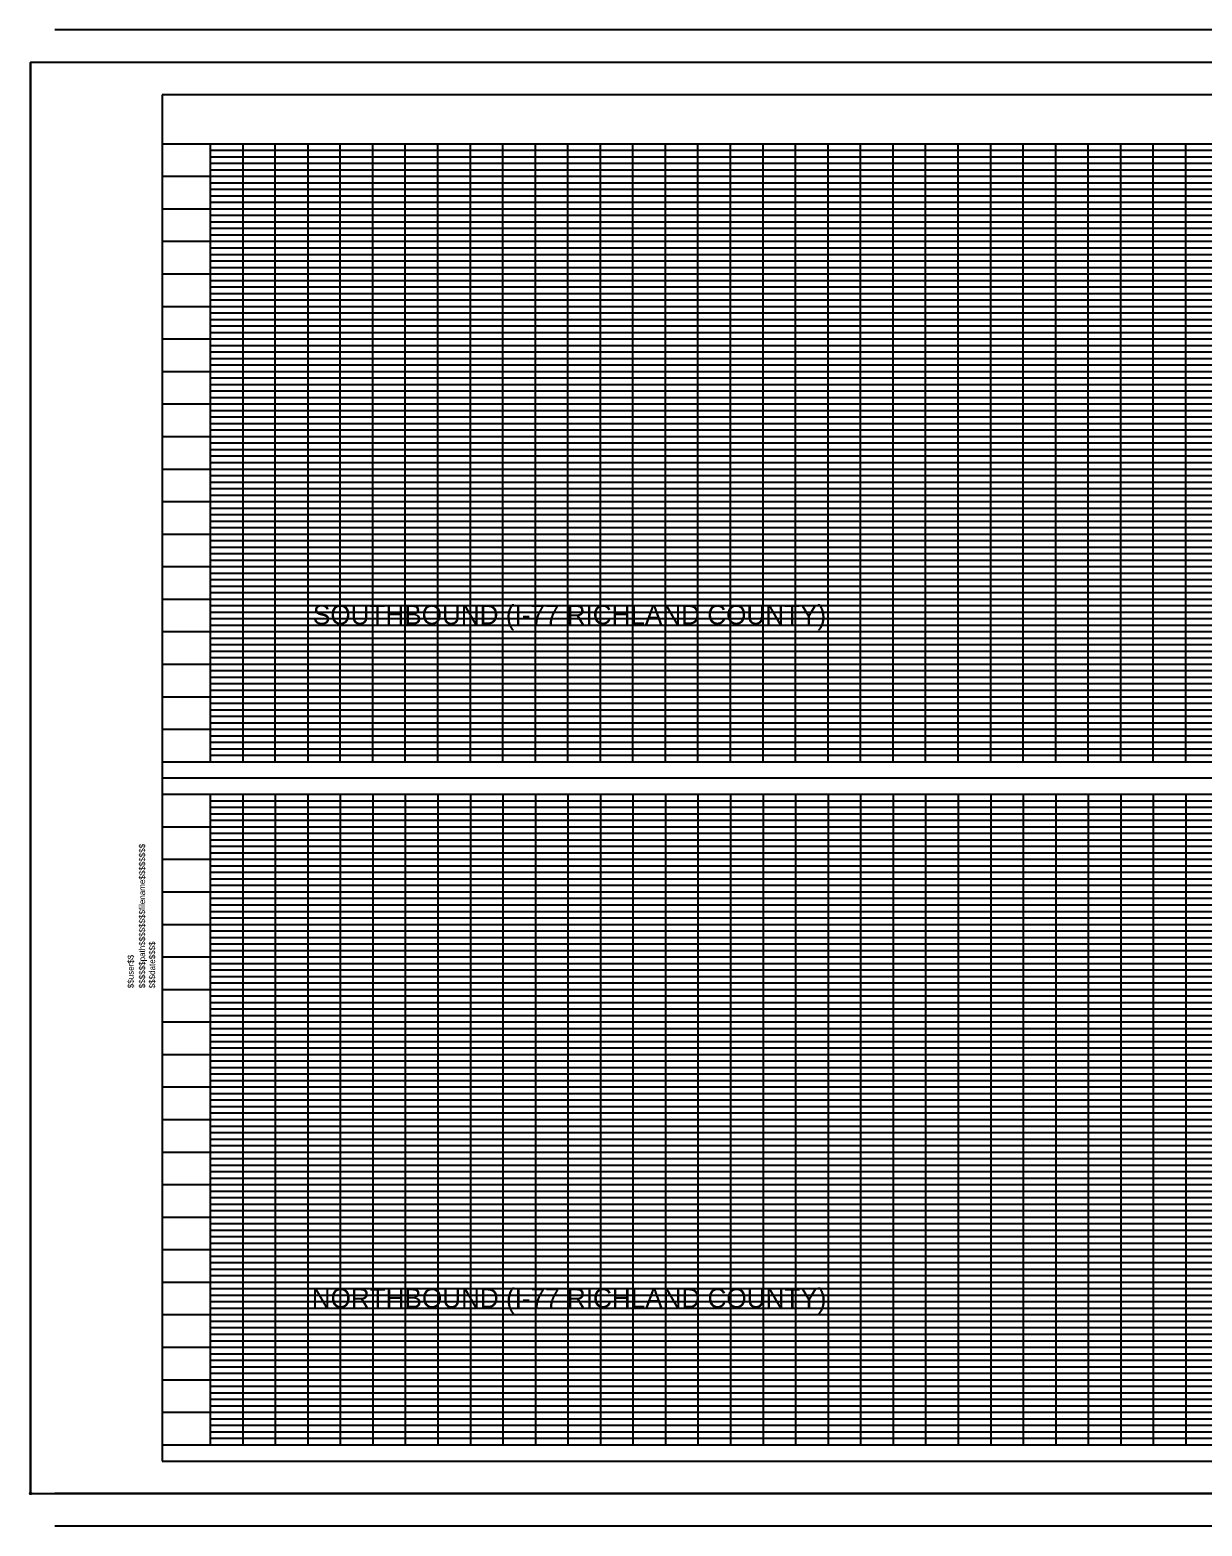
# Model space of a CAD drawing. Extents: x -187 to 1610, y -563 to 587.
# Drawn here: x -187 to 714, y -563 to 587 of the extents above; entities that cross this region are included whole.
import ezdxf

# ---------------------------------------------------------------- set-up
doc = ezdxf.new("R2010")
doc.units = 0
for name, color, linetype in [('Default', 7, 'Continuous'), ('RD_SHT_Bndy', 7, 'Continuous'), ('RD_SHT_ID', 7, 'Continuous'), ('RD_SHT_IplotShp', 7, 'Continuous'), ('RD_SHT_MjGrid', 7, 'Continuous'), ('RD_SHT_MnGrid', 7, 'Continuous'), ('RD_SHT_Snap', 7, 'Continuous'), ('RD_SHT_SubGrid', 7, 'Continuous')]:
    doc.layers.add(name, color=color, linetype=linetype)

msp = doc.modelspace()

# ---------------------------------------------------------------- linework, layer by layer
at = {"layer": 'RD_SHT_Bndy'}
for p, q in [((1592.6, 587.5), (-167.4, 587.5)), ((1592.6, 562.5), (-167.4, 562.5)), ((-85, 537.5), (-85, -512.5)), ((1590, 537.5), (-85, 537.5)), ((-85.5, 500), (1590, 500)), ((-48, 500), (-48, 25)), ((-85, 25), (1590, 25)), ((-85, 12.5), (1590, 12.5)), ((-85, 0), (1590, 0)), ((-48, 0), (-48, -500)), ((-85, -500), (1590.3, -500)), ((-85, -512.5), (1590, -512.5)), ((1592.6, -537.5), (-167.4, -537.5)), ((1592.6, -562.5), (-167.4, -562.5))]:
    msp.add_line(p, q, dxfattribs=at)
at = {"layer": 'RD_SHT_IplotShp'}
msp.add_lwpolyline([(1610, 562.5), (-186, 562.5), (-186, -537.5), (1610, -537.5)], close=True, dxfattribs=at)
at = {"layer": 'RD_SHT_MjGrid'}
for p, q in [((2, 25.1), (2, 500)), ((52, 25), (52, 500)), ((102, 25), (102, 500)), ((152, 24.9), (152, 500)), ((202, 25), (202, 500)), ((252, 25), (252, 500)), ((302, 25.1), (302, 500)), ((352, 25), (352, 500)), ((402, 25), (402, 500)), ((452, 24.9), (452, 500)), ((502, 25), (502, 500)), ((552, 24.9), (552, 500)), ((602, 25), (602, 500)), ((652, 25), (652, 500)), ((702, 24.9), (702, 500)), ((-85, 475), (1452, 475)), ((-85, 425), (1452, 425)), ((-85, 375), (1590, 375)), ((-85, 325), (1590, 325)), ((-85, 275), (1590, 275)), ((-85, 225), (1590, 225)), ((-85, 175), (1590, 175)), ((-85, 125), (1590, 125)), ((-85, 75), (1590, 75)), ((2, 0), (2, -500)), ((52, 0), (52, -500)), ((102, 0), (102, -500)), ((152, 0), (152, -500)), ((202, 0), (202, -500)), ((252, 0), (252, -500)), ((302, 0), (302, -500)), ((352, 0), (352, -500)), ((402, 0), (402, -500)), ((452, 0), (452, -500)), ((502, 0), (502, -500)), ((552, 0), (552, -500)), ((602, 0), (602, -500)), ((652, 0), (652, -500)), ((702, 0), (702, -500)), ((-85, -50), (1590, -50)), ((-85, -100), (1590, -100)), ((-85, -150), (1590, -150)), ((-85, -200), (1590, -200)), ((-85, -250), (1590, -250)), ((-85, -300), (1590, -300)), ((-85, -350), (1590, -350)), ((-85, -400), (1590, -400)), ((-85, -450), (1590, -450))]:
    msp.add_line(p, q, dxfattribs=at)
at = {"layer": 'RD_SHT_MnGrid'}
for p, q in [((-23, 500), (-23, 24.9)), ((27, 500), (27, 24.9)), ((77, 25), (77, 500)), ((127, 25), (127, 500)), ((177, 24.9), (177, 500)), ((227, 25), (227, 500)), ((277, 25.1), (277, 500)), ((327, 25.1), (327, 500)), ((377, 25), (377, 500)), ((427, 24.9), (427, 500)), ((477, 24.9), (477, 500)), ((527, 24.9), (527, 500)), ((577, 24.9), (577, 500)), ((627, 25), (627, 500)), ((677, 25), (677, 500)), ((-85, 450), (1452, 450)), ((-85, 400), (1452, 400)), ((-85, 350), (1590, 350)), ((-85, 300), (1590, 300)), ((-85, 250), (1590, 250)), ((-85, 200), (1590, 200)), ((-85, 150), (1590, 150)), ((-85, 100), (1590, 100)), ((-85, 50), (1590, 50)), ((-23, 0), (-23, -500)), ((27, 0), (27, -500)), ((77, 0), (77, -500)), ((127, 0), (127, -500)), ((177, 0), (177, -500)), ((227, 0), (227, -500)), ((277, 0), (277, -500)), ((327, 0), (327, -500)), ((377, 0), (377, -500)), ((427, 0), (427, -500)), ((477, 0), (477, -500)), ((527, 0), (527, -500)), ((577, 0), (577, -500)), ((627, 0), (627, -500)), ((677, 0), (677, -500)), ((-85, -25), (1590, -25)), ((-85, -75), (1590, -75)), ((-85, -125), (1590, -125)), ((-85, -175), (1590, -175)), ((-85, -225), (1590, -225)), ((-85, -275), (1590, -275)), ((-85, -325), (1590, -325)), ((-85, -375), (1590, -375)), ((-85, -425), (1590, -425)), ((-85, -475), (1590, -475))]:
    msp.add_line(p, q, dxfattribs=at)
at = {"layer": 'RD_SHT_Snap'}
msp.add_line((-186, -537.5), (-186, 562.5), dxfattribs=at)
msp.add_circle((-186, -537.5), 0.607, dxfattribs=at)
at = {"layer": 'RD_SHT_SubGrid'}
for p, q in [((-47.9, 495), (1452, 495)), ((-47.9, 490), (1452, 490)), ((-47.9, 485), (1452, 485)), ((-47.9, 480), (1452, 480)), ((-48, 470), (1452, 470)), ((-48, 465), (1452, 465)), ((-48, 460), (1452, 460)), ((-47.9, 455), (1452, 455)), ((-48, 445), (1452, 445)), ((-48, 440), (1452, 440)), ((-48, 435), (1452, 435)), ((-47.9, 430), (1452, 430)), ((-48, 420), (1452, 420)), ((-48, 415), (1452, 415)), ((-48, 410), (1452, 410)), ((-48, 405), (1452, 405)), ((-47.9, 395), (1452, 395)), ((-48, 390), (1452, 390)), ((-48, 385), (1452, 385)), ((-48, 380), (1452, 380)), ((-47.9, 370), (1551.9, 370)), ((-48, 365), (1551.9, 365)), ((-48, 360), (1551.9, 360)), ((-47.9, 355), (1551.8, 355)), ((-48, 335), (1551.8, 335)), ((-47.9, 345), (1551.6, 345)), ((-47.9, 340), (1551.6, 340)), ((-48, 330), (1551.8, 330)), ((-47.9, 330), (1551.8, 330)), ((-48, 320), (1551.8, 320)), ((-48, 315), (1551.8, 315)), ((-48, 310), (1551.8, 310)), ((-48, 305), (1551.8, 305)), ((-48, 295), (1551.8, 295)), ((-48, 290), (1551.8, 290)), ((-48, 285), (1551.8, 285)), ((-48, 280), (1551.8, 280)), ((-48, 270), (1551.8, 270)), ((-48, 265), (1551.8, 265)), ((-48, 260), (1551.8, 260)), ((-48, 255), (1551.8, 255)), ((-48, 245), (1551.8, 245)), ((-48, 240), (1551.8, 240)), ((-48, 235), (1551.8, 235)), ((-48, 230), (1551.8, 230)), ((-48, 220), (1551.8, 220)), ((-48, 215), (1551.8, 215)), ((-48, 210), (1551.8, 210)), ((-48, 205), (1551.8, 205)), ((-48, 195), (1551.2, 195)), ((-48, 195), (1550.7, 195)), ((-48, 190), (1550.7, 190)), ((-48, 185), (1551.2, 185)), ((-48, 180), (1551.2, 180)), ((-47.9, 170), (1551.2, 170)), ((-47.9, 165), (1551.2, 165)), ((-47.9, 160), (1550.7, 160)), ((-47.9, 155), (1550.7, 155)), ((-48, 145), (1551.2, 145)), ((-48, 140), (1551.2, 140)), ((-48, 135), (1551.2, 135)), ((-48, 130), (1551.2, 130)), ((-47.9, 120), (1551.8, 120)), ((-48, 115), (1550.7, 115)), ((-48, 110), (1551.2, 110)), ((-48, 105), (1550.7, 105)), ((-48, 95), (1551.2, 95)), ((-48, 90), (1551.2, 90)), ((-48, 85), (1550.7, 85)), ((-48, 80), (1550.7, 80)), ((-48, 70), (1551.8, 70)), ((-48, 65), (1551.2, 65)), ((-48, 60), (1551.8, 60)), ((-48, 55), (1551.8, 55)), ((-48, 45), (1551.8, 45)), ((-48, 40), (1551.2, 40)), ((-48, 35), (1550.7, 35)), ((-48, 30), (1551.8, 30)), ((-48, -5), (1551.8, -5)), ((-48, -10), (1551.2, -10)), ((-48, -15), (1551.8, -15)), ((-47.9, -20), (1551.8, -20)), ((-48, -30), (1551.8, -30)), ((-48, -35), (1550.7, -35)), ((-48, -40), (1551.2, -40)), ((-48, -45), (1551.8, -45)), ((-48, -55), (1551.8, -55)), ((-48, -60), (1551.8, -60)), ((-48, -65), (1551.2, -65)), ((-48, -70), (1551.8, -70)), ((-48, -80), (1550.7, -80)), ((-48, -85), (1550.7, -85)), ((-48, -90), (1551.2, -90)), ((-48, -95), (1551.2, -95)), ((-48, -105), (1550.7, -105)), ((-48, -110), (1551.2, -110)), ((-48, -115), (1550.7, -115)), ((-47.9, -120), (1551.8, -120)), ((-48, -130), (1551.2, -130)), ((-48, -135), (1551.2, -135)), ((-48, -140), (1551.2, -140)), ((-48, -145), (1551.2, -145)), ((-47.9, -155), (1550.7, -155)), ((-47.9, -160), (1550.7, -160)), ((-47.9, -165), (1551.2, -165)), ((-47.9, -170), (1551.2, -170)), ((-48, -180), (1551.2, -180)), ((-48, -185), (1551.2, -185)), ((-48, -190), (1550.7, -190)), ((-48, -195), (1551.2, -195)), ((-48, -195), (1550.7, -195)), ((-48, -205), (1551.8, -205)), ((-48, -210), (1551.8, -210)), ((-48, -215), (1551.8, -215)), ((-48, -220), (1551.8, -220)), ((-48, -230), (1551.8, -230)), ((-48, -235), (1551.8, -235)), ((-48, -240), (1551.8, -240)), ((-48, -245), (1551.8, -245)), ((-48, -255), (1551.8, -255)), ((-48, -260), (1551.8, -260)), ((-48, -265), (1551.8, -265)), ((-48, -270), (1551.8, -270)), ((-48, -280), (1551.8, -280)), ((-48, -285), (1551.8, -285)), ((-48, -290), (1551.8, -290)), ((-48, -295), (1551.8, -295)), ((-48, -305), (1551.8, -305)), ((-48, -310), (1551.8, -310)), ((-48, -315), (1551.8, -315)), ((-48, -320), (1551.8, -320)), ((-48, -330), (1551.8, -330)), ((-47.9, -330), (1551.8, -330)), ((-48, -335), (1551.8, -335)), ((-47.9, -340), (1551.6, -340)), ((-47.9, -345), (1551.6, -345)), ((-47.9, -355), (1551.8, -355)), ((-48, -360), (1551.9, -360)), ((-48, -365), (1551.9, -365)), ((-47.9, -370), (1551.9, -370)), ((-48, -380), (1551.9, -380)), ((-48, -385), (1551.9, -385)), ((-48, -390), (1551.9, -390)), ((-47.9, -395), (1551.9, -395)), ((-48, -405), (1551.9, -405)), ((-48, -410), (1551.9, -410)), ((-48, -415), (1551.9, -415)), ((-48, -420), (1551.8, -420)), ((-48, -435), (1551.8, -435)), ((-47.9, -430), (1551.6, -430)), ((-48, -440), (1551.8, -440)), ((-48, -445), (1551.8, -445)), ((-47.9, -455), (1551.8, -455)), ((-48, -460), (1551.8, -460)), ((-48, -465), (1551.8, -465)), ((-48, -470), (1551.8, -470)), ((-47.9, -480), (1551.8, -480)), ((-47.9, -485), (1551.8, -485)), ((-47.9, -490), (1551.8, -490)), ((-47.9, -495), (1551.8, -495))]:
    msp.add_line(p, q, dxfattribs=at)

# ---------------------------------------------------------------- texts
at = {"layer": 'Default'}
for s, p in [('SOUTHBOUND (I-77 RICHLAND COUNTY)', (31, 130.5)), ('NORTHBOUND (I-77 RICHLAND COUNTY)', (30.1, -394.8))]:
    msp.add_text(s, height=15, dxfattribs=at).set_placement(p)
at = {"layer": 'RD_SHT_ID'}
for s, p in [('$$$$$$path$$$$$$$$filename$$$$$$$$', (-98, -149.1)), ('$$$date$$$$', (-90.3, -149.2)), ('$$user$$', (-106.8, -149.1))]:
    msp.add_text(s, height=4.62, rotation=90, dxfattribs=at).set_placement(p)

doc.saveas('drawing.dxf')
